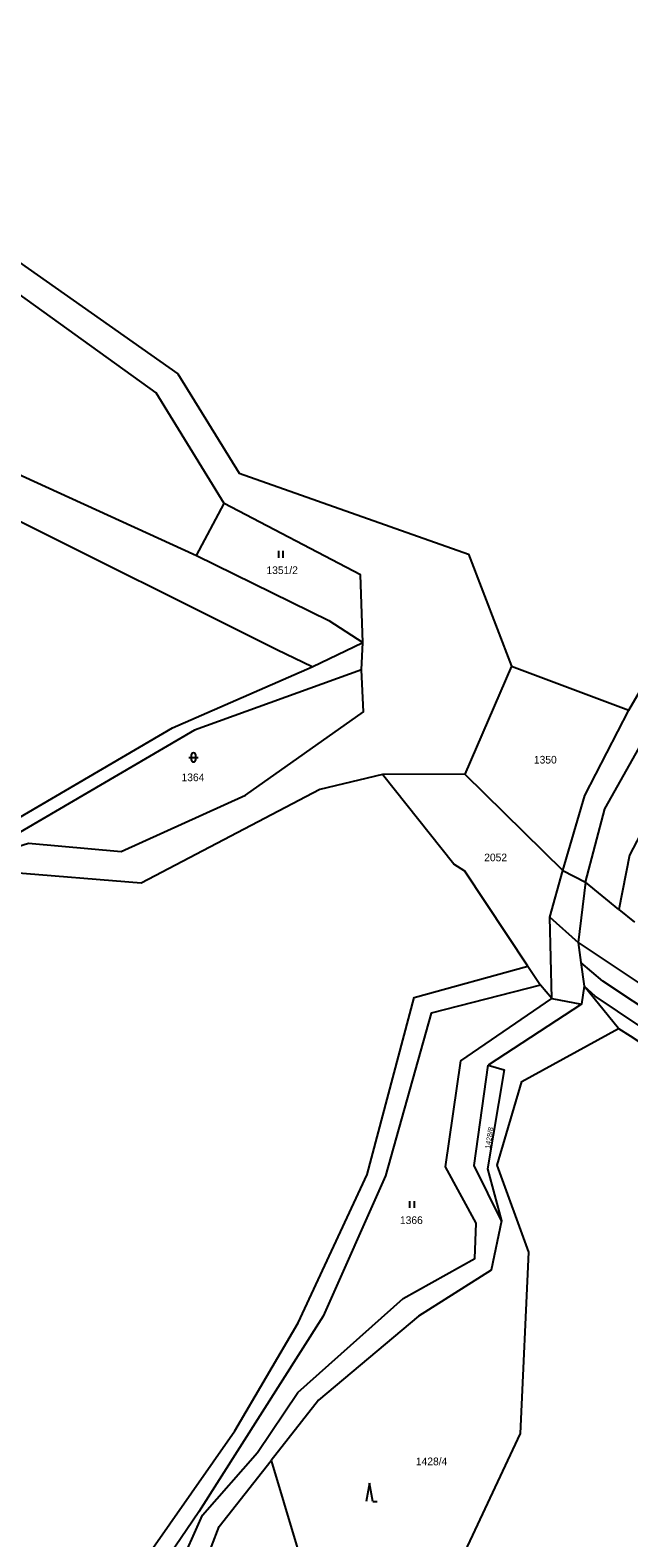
# Model space of a CAD drawing. Extents: x -679220 to -673243, y -1075091 to -1066557.
# Drawn here: x -677968.8 to -677836.3, y -1070402.6 to -1070068.5 of the extents above; entities that cross this region are included whole.
import ezdxf

# ---------------------------------------------------------------- set-up
doc = ezdxf.new("R2010")
doc.units = 0
for name, color, linetype in [('Hranice parcel', 7, 'Continuous'), ('Parcelní čísla', 7, 'Continuous'), ('Vnitřní kresba', 7, 'Continuous'), ('Značky kultur', 7, 'Continuous')]:
    doc.layers.add(name, color=color, linetype=linetype)

msp = doc.modelspace()

# ---------------------------------------------------------------- linework, layer by layer
at = {"layer": 'Hranice parcel'}
for p, q in [((-677932, -1070184.92), (-677925.88, -1070173.41)), ((-677906.4, -1070209.58), (-677895.15, -1070204.18)), ((-677895.43, -1070210.25), (-677895.15, -1070204.18)), ((-677862.25, -1070209.47), (-677872.58, -1070233.36)), ((-677862.25, -1070209.47), (-677836.26, -1070219.22)), ((-677872.58, -1070233.36), (-677890.82, -1070233.42)), ((-677872.58, -1070233.36), (-677850.89, -1070254.75)), ((-677845.88, -1070257.33), (-677847.48, -1070270.67)), ((-677838.43, -1070263.34), (-677845.88, -1070257.33)), ((-677838.43, -1070263.34), (-677834.96, -1070266.14)), ((-677847.48, -1070270.67), (-677787.98, -1070310.51)), ((-677858.64, -1070275.93), (-677855.84, -1070280.12)), ((-677853.32, -1070283.11), (-677855.84, -1070280.12)), ((-677838.54, -1070289.74), (-677846.16, -1070280.35))]:
    msp.add_line(p, q, dxfattribs=at)
for points in [[(-678041.18, -1069909.02), (-678065.15, -1069950.67), (-678094.01, -1070015.39), (-678107.03, -1070019.76), (-678114.92, -1070033.29), (-678100.58, -1070060.16), (-678084.13, -1070078.81), (-678075.06, -1070085.61), (-678057.81, -1070093.45), (-678042.38, -1070094.58), (-678030.11, -1070109.24), (-678025.36, -1070110.53), (-678005.5, -1070102.65), (-677992.5, -1070105), (-677936.08, -1070144.66), (-677922.53, -1070166.67), (-677871.77, -1070184.59), (-677862.25, -1070209.47)], [(-677836.26, -1070219.22), (-677809.01, -1070172.38), (-677805.17, -1070156.15), (-677802.89, -1070127.98), (-677812.51, -1070092.7), (-677809.68, -1070064.56), (-677797.85, -1070049.79)], [(-677925.88, -1070173.41), (-677940.89, -1070148.89), (-677994.8, -1070110.07), (-678007.61, -1070109.88), (-678025.68, -1070115.83), (-678035.07, -1070112.83), (-678044.93, -1070099.85), (-678060.5, -1070099.07), (-678069.75, -1070094.52)], [(-678079.9, -1070112.56), (-678066.78, -1070120.01), (-678024.47, -1070141.35), (-677970.59, -1070167.29), (-677932, -1070184.92)], [(-677845.88, -1070257.33), (-677841.59, -1070241.09), (-677803.79, -1070173.83), (-677799.59, -1070160.2), (-677798.79, -1070126.56)], [(-677906.4, -1070209.58), (-677914.18, -1070205.83), (-677974.75, -1070175.56), (-678029.31, -1070151.45), (-678066.22, -1070131.68), (-678072.15, -1070129.16)], [(-677895.15, -1070204.18), (-677895.7, -1070189.17), (-677925.88, -1070173.41)], [(-677740.82, -1070222.17), (-677797.35, -1070177.34), (-677836.07, -1070251.29), (-677838.43, -1070263.34)], [(-677932, -1070184.92), (-677902.65, -1070199.3), (-677895.15, -1070204.18)], [(-677974.33, -1070244.8), (-677937.29, -1070223.09), (-677906.4, -1070209.58)], [(-677895.43, -1070210.25), (-677932.43, -1070223.6), (-677973.13, -1070247.45)], [(-677971.55, -1070249.37), (-677969.15, -1070248.65), (-677948.62, -1070250.51), (-677921.15, -1070238.04), (-677894.98, -1070219.54), (-677895.43, -1070210.25)], [(-677850.89, -1070254.75), (-677846.02, -1070238.14), (-677836.26, -1070219.22)], [(-677890.82, -1070233.42), (-677904.67, -1070236.77), (-677944.24, -1070257.5), (-677973.23, -1070255.18), (-678021.28, -1070279.34), (-678051.71, -1070287.6), (-678064.16, -1070293.06), (-678078.81, -1070319.75), (-678099.52, -1070331.71), (-678143.71, -1070383.64), (-678142.72, -1070417.02), (-678174.66, -1070435.49), (-678169.23, -1070445.84), (-678170.92, -1070449.74), (-678204.85, -1070471.94), (-678215.92, -1070471.2), (-678224.89, -1070483.14), (-678219.69, -1070499.47), (-678190.89, -1070518.74), (-678188.32, -1070527.54), (-678194.83, -1070553.12), (-678202.72, -1070559.59)], [(-677858.64, -1070275.93), (-677872.57, -1070254.85), (-677874.99, -1070253.35), (-677890.82, -1070233.42)], [(-677853.32, -1070283.11), (-677853.77, -1070265.04), (-677850.89, -1070254.75)], [(-677847.48, -1070270.67), (-677846.88, -1070275.1), (-677846.16, -1070280.35)], [(-678202.72, -1070559.59), (-678196.24, -1070560.72), (-678173.74, -1070562.48), (-678126.52, -1070533.09), (-678089.52, -1070509.78), (-678070.97, -1070501.74), (-678009.17, -1070456.93), (-677947.5, -1070413.22), (-677923.47, -1070378.9), (-677909.43, -1070354.95), (-677894.19, -1070322.1), (-677883.78, -1070282.87), (-677858.64, -1070275.93)], [(-677855.84, -1070280.12), (-677880.02, -1070286.32), (-677890.13, -1070322.37), (-677903.96, -1070353.51), (-677931.48, -1070396.8), (-677944.62, -1070416.2)], [(-677846.16, -1070280.35), (-677846.76, -1070284.31), (-677867.43, -1070297.87)], [(-677944.62, -1070416.2), (-677936.01, -1070409.66), (-677930.66, -1070397.57), (-677918.45, -1070383.68), (-677909.53, -1070370.43), (-677886.19, -1070349.6), (-677870.36, -1070340.73), (-677870.09, -1070332.9), (-677876.85, -1070320.41), (-677873.44, -1070296.89), (-677853.32, -1070283.11)], [(-677876.21, -1070485.99), (-677879.53, -1070478.23), (-677880.65, -1070457.46), (-677876.4, -1070414), (-677860.23, -1070379.46), (-677858.39, -1070339.32), (-677865.38, -1070320.02), (-677859.97, -1070301.48), (-677838.54, -1070289.74)], [(-677838.54, -1070289.74), (-677835.99, -1070291.35), (-677768.72, -1070335.34), (-677756.66, -1070345.34)], [(-677864.46, -1070332.36), (-677870.51, -1070320.11), (-677867.43, -1070297.87)], [(-677867.43, -1070297.87), (-677863.87, -1070298.91), (-677867.54, -1070320.85), (-677864.46, -1070332.36)], [(-677864.46, -1070332.36), (-677866.74, -1070343.31), (-677882.79, -1070353.48), (-677904.98, -1070372.06), (-677915.46, -1070385.44)], [(-677934.76, -1070416.68), (-677932.07, -1070413.36), (-677926.94, -1070400.09), (-677915.46, -1070385.44)], [(-677915.46, -1070385.44), (-677901.39, -1070432.37), (-677897.5, -1070454.86), (-677890.42, -1070473.63)]]:
    msp.add_lwpolyline(points, dxfattribs=at)
at = {"layer": 'Vnitřní kresba'}
for p, q in [((-677850.89, -1070254.75), (-677845.88, -1070257.33)), ((-677853.77, -1070265.04), (-677847.48, -1070270.67)), ((-677841.98, -1070279.26), (-677846.88, -1070275.1)), ((-677843.71, -1070282.56), (-677846.16, -1070280.35)), ((-677767.61, -1070328.87), (-677841.98, -1070279.26)), ((-677853.32, -1070283.11), (-677846.76, -1070284.31)), ((-677770.23, -1070331.96), (-677843.71, -1070282.56))]:
    msp.add_line(p, q, dxfattribs=at)
at = {"layer": 'Značky kultur'}
for p, q in [((-677913.78, -1070185.42), (-677913.78, -1070183.92)), ((-677912.78, -1070185.42), (-677912.78, -1070183.92)), ((-677933.64, -1070229.65), (-677931.64, -1070229.65)), ((-677933.14, -1070229.15), (-677933.14, -1070230.15)), ((-677932.14, -1070230.15), (-677932.14, -1070229.15)), ((-677884.71, -1070329.51), (-677884.71, -1070328.01)), ((-677883.71, -1070329.51), (-677883.71, -1070328.01)), ((-677893.69, -1070390.52), (-677894.44, -1070394.52)), ((-677892.94, -1070394.52), (-677893.69, -1070390.52)), ((-677892.94, -1070394.52), (-677891.94, -1070394.52))]:
    msp.add_line(p, q, dxfattribs=at)
for centre, start, end in [((-677932.64, -1070229.15), 0, 180), ((-677932.64, -1070230.15), 180, 359.9879)]:
    msp.add_arc(centre, 0.5, start, end, dxfattribs=at)

# ---------------------------------------------------------------- texts
at = {"layer": 'Parcelní čísla'}
for s, p in [('1351/2', (-677916.48, -1070189.03)), ('1350', (-677857.27, -1070231.02)), ('1364', (-677935.29, -1070234.93)), ('2052', (-677868.27, -1070252.68)), ('1366', (-677886.93, -1070333.06)), ('1428/4', (-677883.4, -1070386.51))]:
    msp.add_text(s, height=1.7, dxfattribs=at).set_placement(p)
msp.add_text('1428/8', height=1.14, rotation=81, dxfattribs=at).set_placement((-677866.98, -1070316.44))

doc.saveas('drawing.dxf')
